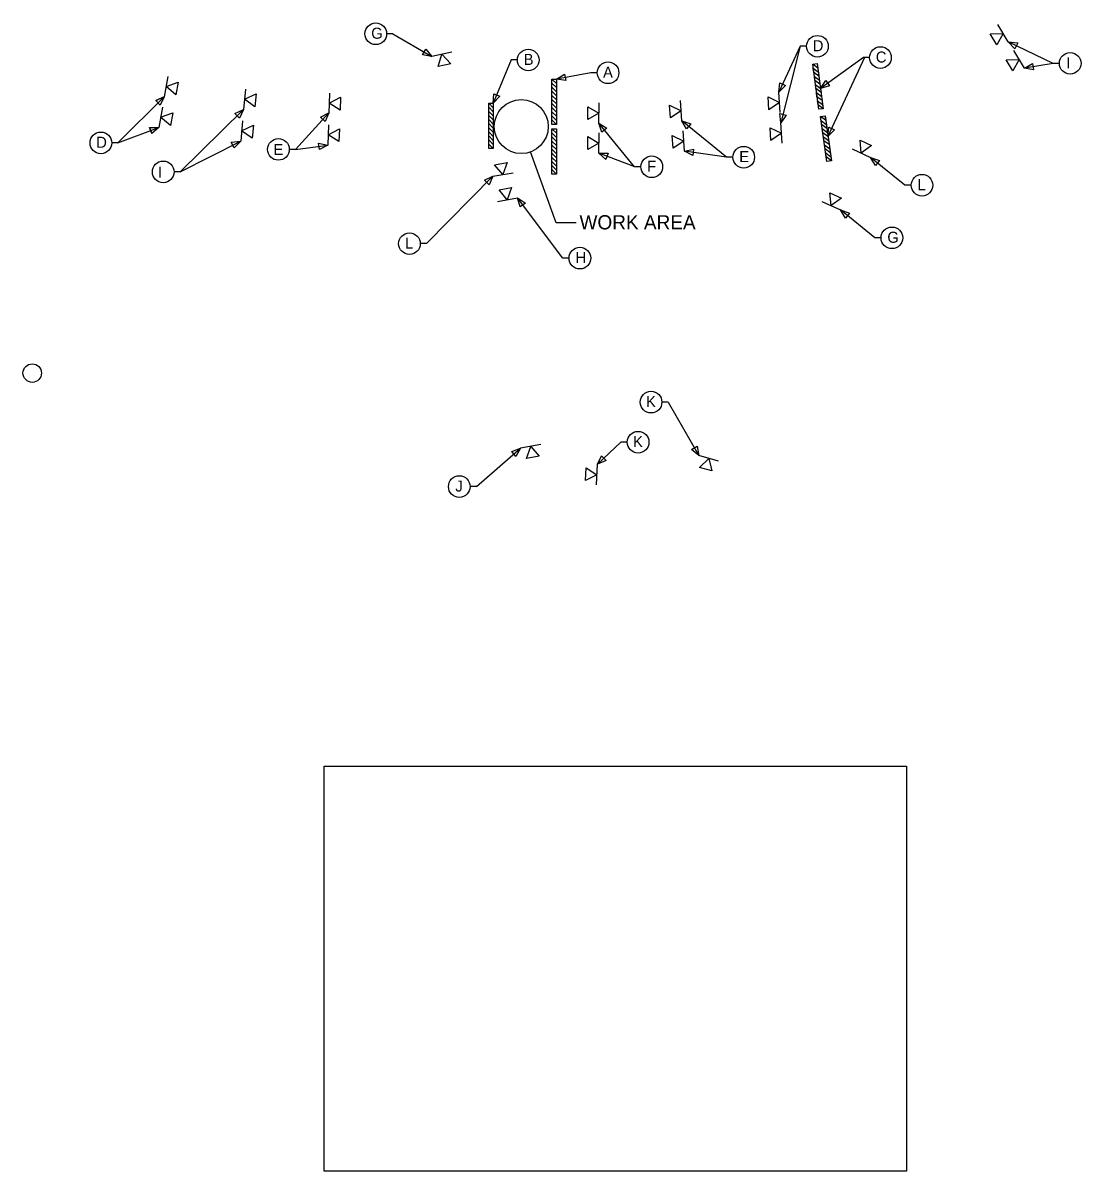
# Model space of a CAD drawing. Extents: x 2157572 to 5059327, y 715220 to 1674494.
# Drawn here: x 2244468 to 2251167, y 723646 to 730920 of the extents above; entities that cross this region are included whole.
import ezdxf

# ---------------------------------------------------------------- set-up
doc = ezdxf.new("R2010")
doc.units = 0
for name, color, linetype in [('Exist Map Preparation Border Sheet 1 CELL', 7, 'Continuous'), ('Exist Road Primary US Structure Standard Bridge Number Label', 7, 'Continuous'), ('Exist Road Secondary Structure Pipe Number Label', 7, 'Continuous'), ('Exist Road Secondary Type 41 SR Number Label', 7, 'Continuous'), ('Level 51', 7, 'Continuous'), ('Map Preparation County Base Legend Highway Garage or Maintenance Office', 7, 'Continuous')]:
    doc.layers.add(name, color=color, linetype=linetype)

msp = doc.modelspace()

# ---------------------------------------------------------------- linework, layer by layer
at = {"layer": 'Exist Map Preparation Border Sheet 1 CELL'}
msp.add_lwpolyline([(2250061.6, 723646.4), (2246376, 723646.4), (2246376, 726211.5), (2250061.6, 726211.5)], close=True, dxfattribs=at)
at = {"layer": 'Exist Road Secondary Structure Pipe Number Label'}
for p, q in [((2250707.1, 730799.8), (2250640, 730910.7)), ((2250592.7, 730852.2), (2250674.2, 730854.1)), ((2250634.8, 730782.8), (2250592.7, 730852.2)), ((2250674.2, 730854.1), (2250634.8, 730782.8)), ((2247183.1, 730736.2), (2247056.7, 730707.5)), ((2247097.3, 730644.2), (2247121.2, 730722.2)), ((2247121.2, 730722.2), (2247176.5, 730662.2)), ((2250694.3, 730686.9), (2250775.8, 730688.8)), ((2250736.4, 730617.4), (2250694.3, 730686.9)), ((2250775.8, 730688.8), (2250736.4, 730617.4)), ((2250808.7, 730634.5), (2250741.6, 730745.3)), ((2247176.5, 730662.2), (2247097.3, 730644.2)), ((2245385.6, 730580.5), (2245362.6, 730453)), ((2245374.3, 730518), (2245451.1, 730545.4)), ((2245451.1, 730545.4), (2245436.7, 730465.5)), ((2245436.7, 730465.5), (2245374.3, 730518)), ((2245876, 730500.2), (2245864, 730371.2)), ((2245870.1, 730437), (2245944.3, 730470.9)), ((2245944.3, 730470.9), (2245936.7, 730390)), ((2246409.1, 730475.6), (2246404, 730346.1)), ((2249263.2, 730352.4), (2249254.4, 730481.7)), ((2245351, 730386), (2245328, 730258.5)), ((2245936.7, 730390), (2245870.1, 730437)), ((2246406.6, 730412.1), (2246478.8, 730449.9)), ((2246475.7, 730368.8), (2246406.6, 730412.1)), ((2246478.8, 730449.9), (2246475.7, 730368.8)), ((2248043.8, 730308.5), (2248045.1, 730389.7)), ((2248045.1, 730389.7), (2248115.1, 730348)), ((2248114.1, 730284.5), (2248116.2, 730414.1)), ((2248562.3, 730399.5), (2248635.6, 730363.8)), ((2248567.9, 730318.5), (2248562.3, 730399.5)), ((2248639.9, 730300.5), (2248631.1, 730429.8)), ((2249185.6, 730451.5), (2249258.9, 730415.8)), ((2249191.1, 730370.5), (2249185.6, 730451.5)), ((2249258.9, 730415.8), (2249191.1, 730370.5)), ((2245339.8, 730323.5), (2245416.5, 730350.9)), ((2245402.1, 730271.1), (2245339.8, 730323.5)), ((2245416.5, 730350.9), (2245402.1, 730271.1)), ((2248115.1, 730348), (2248043.8, 730308.5)), ((2248635.6, 730363.8), (2248567.9, 730318.5)), ((2245858.6, 730301.2), (2245846.6, 730172.2)), ((2245852.7, 730238), (2245926.8, 730271.9)), ((2245926.8, 730271.9), (2245919.3, 730191.1)), ((2246402.4, 730275.9), (2246397.4, 730146.4)), ((2246399.9, 730212.5), (2246472.1, 730250.3)), ((2246472.1, 730250.3), (2246469, 730169.2)), ((2249198.3, 730257), (2249271.6, 730221.3)), ((2249203.8, 730176), (2249198.3, 730257)), ((2249275.9, 730157.9), (2249267.1, 730287.2)), ((2245919.3, 730191.1), (2245852.7, 730238)), ((2246469, 730169.2), (2246399.9, 730212.5)), ((2248043.8, 730119.5), (2248045.1, 730200.7)), ((2248045.1, 730200.7), (2248115.1, 730158.9)), ((2248114.1, 730095.4), (2248116.2, 730225)), ((2248578.7, 730207.7), (2248651.9, 730172)), ((2248584.2, 730126.7), (2248578.7, 730207.7)), ((2248651.9, 730172), (2248584.2, 730126.7)), ((2248656.3, 730108.6), (2248647.5, 730237.9)), ((2249271.6, 730221.3), (2249203.8, 730176)), ((2249775.3, 730096.5), (2249768, 730177.7)), ((2249768, 730177.7), (2249841.7, 730143.8)), ((2248115.1, 730158.9), (2248043.8, 730119.5)), ((2249717.6, 730123.1), (2249835.3, 730068.9)), ((2249841.7, 730143.8), (2249775.3, 730096.5)), ((2247454.5, 730022.3), (2247534.4, 730036.3)), ((2247506.6, 729959.7), (2247454.5, 730022.3)), ((2247534.4, 730036.3), (2247506.6, 729959.7)), ((2247444, 729948.8), (2247571.7, 729971)), ((2247482.2, 729863), (2247562.1, 729876.9)), ((2247562.1, 729876.9), (2247534.3, 729800.3)), ((2247471.7, 729789.4), (2247599.4, 729811.6)), ((2247534.3, 729800.3), (2247482.2, 729863)), ((2249584.8, 729763), (2249577.2, 729844.2)), ((2249577.2, 729844.2), (2249651, 729810.5)), ((2249651, 729810.5), (2249584.8, 729763)), ((2249527, 729789.3), (2249645, 729735.6)), ((2247746, 728248.8), (2247618.3, 728226.6)), ((2247655.6, 728161.3), (2247683.5, 728237.9)), ((2247683.5, 728237.9), (2247735.6, 728175.2)), ((2247735.6, 728175.2), (2247655.6, 728161.3)), ((2248871.8, 728144), (2248747.2, 728179.7)), ((2248752.2, 728104.7), (2248810.7, 728161.5)), ((2248810.7, 728161.5), (2248830.3, 728082.3)), ((2248029.7, 728020.9), (2248033.6, 728102)), ((2248102.3, 728058), (2248029.7, 728020.9)), ((2248033.6, 728102), (2248102.3, 728058)), ((2248099.2, 727994.6), (2248105.5, 728124.1)), ((2248830.3, 728082.3), (2248752.2, 728104.7))]:
    msp.add_line(p, q, dxfattribs=at)
at = {"layer": 'Exist Road Secondary Type 41 SR Number Label'}
for p, q in [((2249468.7, 730658.9), (2249497.3, 730662.6)), ((2249501, 730634.5), (2249468.7, 730658.9)), ((2249469.2, 730659), (2249497.3, 730662.6)), ((2249506.4, 730373.5), (2249469.2, 730659)), ((2249472.1, 730633.2), (2249504.3, 730608.8)), ((2249475.4, 730607.5), (2249472.1, 730633.2)), ((2249507.7, 730583.2), (2249475.4, 730607.5)), ((2249497.3, 730662.6), (2249501, 730634.5)), ((2249497.3, 730662.6), (2249534.5, 730377.2)), ((2249504.3, 730608.8), (2249507.7, 730583.2)), ((2247817, 730565.2), (2247845.8, 730565.2)), ((2247845.8, 730536.9), (2247817, 730565.2)), ((2247817, 730539.3), (2247845.8, 730511)), ((2247817, 730513.4), (2247817, 730539.3)), ((2247817.5, 730277.4), (2247817.5, 730565.2)), ((2247817.5, 730565.2), (2247845.8, 730565.2)), ((2247845.8, 730565.2), (2247845.8, 730536.9)), ((2247845.8, 730565.2), (2247845.8, 730277.4)), ((2249478.8, 730581.9), (2249511, 730557.5)), ((2249482.1, 730556.2), (2249478.8, 730581.9)), ((2249514.4, 730531.8), (2249482.1, 730556.2)), ((2249485.5, 730530.5), (2249517.7, 730506.1)), ((2249488.8, 730504.8), (2249485.5, 730530.5)), ((2249511, 730557.5), (2249514.4, 730531.8)), ((2247845.8, 730485.1), (2247817, 730513.4)), ((2247817, 730487.5), (2247845.8, 730459.2)), ((2247817, 730461.6), (2247817, 730487.5)), ((2247845.8, 730433.3), (2247817, 730461.6)), ((2247845.8, 730511), (2247845.8, 730485.1)), ((2247845.8, 730459.2), (2247845.8, 730433.3)), ((2249521.1, 730480.4), (2249488.8, 730504.8)), ((2249492.2, 730479.1), (2249524.5, 730454.3)), ((2249495.5, 730453.4), (2249492.2, 730479.1)), ((2249517.7, 730506.1), (2249521.1, 730480.4)), ((2247417.4, 730412), (2247446.2, 730412)), ((2247446.2, 730383.7), (2247417.4, 730412)), ((2247417.4, 730386.1), (2247446.2, 730357.8)), ((2247417.4, 730360.2), (2247417.4, 730386.1)), ((2247417.9, 730124.2), (2247417.9, 730412)), ((2247417.9, 730412), (2247446.2, 730412)), ((2247446.2, 730412), (2247446.2, 730383.7)), ((2247446.2, 730412), (2247446.2, 730124.2)), ((2247817, 730435.7), (2247845.8, 730407.4)), ((2247817, 730409.8), (2247817, 730435.7)), ((2247845.8, 730381.5), (2247817, 730409.8)), ((2247845.8, 730407.4), (2247845.8, 730381.5)), ((2249527.8, 730428.6), (2249495.5, 730453.4)), ((2249498.9, 730427.8), (2249531.2, 730402.9)), ((2249502.2, 730402.1), (2249498.9, 730427.8)), ((2249534.5, 730377.2), (2249502.2, 730402.1)), ((2249524.5, 730454.3), (2249527.8, 730428.6)), ((2249531.2, 730402.9), (2249534.5, 730377.2)), ((2247446.2, 730331.9), (2247417.4, 730360.2)), ((2247417.4, 730334.3), (2247446.2, 730306)), ((2247417.4, 730308.4), (2247417.4, 730334.3)), ((2247446.2, 730357.8), (2247446.2, 730331.9)), ((2247817, 730383.9), (2247845.8, 730355.1)), ((2247817, 730358), (2247817, 730383.9)), ((2247845.8, 730329.2), (2247817, 730358)), ((2247817, 730332.1), (2247845.8, 730303.3)), ((2247817, 730306.2), (2247817, 730332.1)), ((2247845.8, 730355.1), (2247845.8, 730329.2)), ((2249534.5, 730377.2), (2249506.4, 730373.5)), ((2249517.8, 730327.6), (2249546.4, 730331.7)), ((2249550.4, 730303.6), (2249517.8, 730327.6)), ((2249518.3, 730327.7), (2249546.4, 730331.7)), ((2249558.9, 730042.7), (2249518.3, 730327.7)), ((2249546.4, 730331.7), (2249550.4, 730303.6)), ((2249546.4, 730331.7), (2249587, 730046.7)), ((2247446.2, 730280.1), (2247417.4, 730308.4)), ((2247417.4, 730282.5), (2247446.2, 730254.2)), ((2247417.4, 730256.6), (2247417.4, 730282.5)), ((2247446.2, 730228.3), (2247417.4, 730256.6)), ((2247446.2, 730306), (2247446.2, 730280.1)), ((2247446.2, 730254.2), (2247446.2, 730228.3)), ((2247845.8, 730277.4), (2247817, 730306.2)), ((2247817, 730250), (2247845.8, 730250)), ((2247845.8, 730221.6), (2247817, 730250)), ((2247845.8, 730277.4), (2247817.5, 730277.4)), ((2247817.5, 729962.1), (2247817.5, 730250)), ((2247817.5, 730250), (2247845.8, 730250)), ((2247845.8, 730303.3), (2247845.8, 730277.4)), ((2247845.8, 730250), (2247845.8, 730221.6)), ((2247845.8, 730250), (2247845.8, 729962.1)), ((2249521.5, 730302), (2249554, 730278)), ((2249525.1, 730276.4), (2249521.5, 730302)), ((2249557.7, 730252.4), (2249525.1, 730276.4)), ((2249528.8, 730250.7), (2249561.3, 730226.7)), ((2249532.4, 730225.1), (2249528.8, 730250.7)), ((2249554, 730278), (2249557.7, 730252.4)), ((2247417.4, 730230.7), (2247446.2, 730201.9)), ((2247417.4, 730204.8), (2247417.4, 730230.7)), ((2247446.2, 730176), (2247417.4, 730204.8)), ((2247417.4, 730178.9), (2247446.2, 730150.1)), ((2247417.4, 730153), (2247417.4, 730178.9)), ((2247446.2, 730201.9), (2247446.2, 730176)), ((2247817, 730224.1), (2247845.8, 730195.7)), ((2247817, 730198.2), (2247817, 730224.1)), ((2247845.8, 730169.8), (2247817, 730198.2)), ((2247817, 730172.3), (2247845.8, 730143.9)), ((2247817, 730146.4), (2247817, 730172.3)), ((2247845.8, 730195.7), (2247845.8, 730169.8)), ((2249565, 730201.1), (2249532.4, 730225.1)), ((2249536.1, 730199.4), (2249568.7, 730175.4)), ((2249539.8, 730173.8), (2249536.1, 730199.4)), ((2249572.3, 730149.8), (2249539.8, 730173.8)), ((2249561.3, 730226.7), (2249565, 730201.1)), ((2249568.7, 730175.4), (2249572.3, 730149.8)), ((2247446.2, 730124.2), (2247417.4, 730153)), ((2247446.2, 730124.2), (2247417.9, 730124.2)), ((2247446.2, 730150.1), (2247446.2, 730124.2)), ((2247845.8, 730118), (2247817, 730146.4)), ((2247817, 730120.5), (2247845.8, 730092.1)), ((2247817, 730094.6), (2247817, 730120.5)), ((2247845.8, 730066.2), (2247817, 730094.6)), ((2247845.8, 730143.9), (2247845.8, 730118)), ((2249543.4, 730148.1), (2249576, 730123.7)), ((2249547.1, 730122.5), (2249543.4, 730148.1)), ((2249579.7, 730098), (2249547.1, 730122.5)), ((2249550.7, 730096.9), (2249583.3, 730072.4)), ((2249554.4, 730071.2), (2249550.7, 730096.9)), ((2249576, 730123.7), (2249579.7, 730098)), ((2247817, 730068.7), (2247845.8, 730039.8)), ((2247817, 730042.8), (2247817, 730068.7)), ((2247845.8, 730013.9), (2247817, 730042.8)), ((2247845.8, 730092.1), (2247845.8, 730066.2)), ((2247845.8, 730039.8), (2247845.8, 730013.9)), ((2249587, 730046.7), (2249554.4, 730071.2)), ((2249587, 730046.7), (2249558.9, 730042.7)), ((2249583.3, 730072.4), (2249587, 730046.7)), ((2247817, 730016.9), (2247845.8, 729988)), ((2247817, 729991), (2247817, 730016.9)), ((2247845.8, 729962.1), (2247817, 729991)), ((2247845.8, 729962.1), (2247817.5, 729962.1)), ((2247845.8, 729988), (2247845.8, 729962.1))]:
    msp.add_line(p, q, dxfattribs=at)
at = {"layer": 'Level 51'}
for p, q in [((2246810.1, 730851.8), (2246770.5, 730851.8)), ((2246810.1, 730851.8), (2247056.7, 730707.5)), ((2249390, 730772.6), (2249254.4, 730481.7)), ((2249390, 730772.6), (2249267.1, 730287.2)), ((2249429.6, 730772.6), (2249390, 730772.6)), ((2250990.6, 730664.6), (2250707.1, 730799.8)), ((2247559.3, 730685.8), (2247446.2, 730412)), ((2247598.9, 730685.8), (2247559.3, 730685.8)), ((2249789.4, 730700.9), (2249517.7, 730506.1)), ((2249797.1, 730700.9), (2249565, 730201.1)), ((2249829, 730700.9), (2249789.4, 730700.9)), ((2248064.4, 730604.9), (2247845.8, 730565.2)), ((2248104, 730604.9), (2248064.4, 730604.9)), ((2250990.6, 730664.6), (2250808.7, 730634.5)), ((2251030.2, 730664.6), (2250990.6, 730664.6)), ((2245069.5, 730160.8), (2245362.6, 730453)), ((2245362.6, 730453), (2245308.2, 730428.1)), ((2245308.2, 730428.1), (2245337.5, 730398.7)), ((2245362.6, 730453), (2245337.5, 730398.7)), ((2245464.1, 729976.5), (2245864, 730371.2)), ((2246193.9, 730119.5), (2246404.2, 730351)), ((2245069.5, 730160.8), (2245328, 730258.5)), ((2245268.3, 730258.1), (2245282.9, 730219.3)), ((2248340.9, 730009), (2248114.1, 730284.5)), ((2248923.2, 730070), (2248639.9, 730300.5)), ((2245464.1, 729976.5), (2245846.6, 730172.2)), ((2245069.5, 730160.8), (2245029.9, 730160.8)), ((2246193.9, 730119.5), (2246154.3, 730119.5)), ((2246193.9, 730119.5), (2246397.4, 730146.4)), ((2247844.2, 729654.2), (2247681.7, 730103.4)), ((2248342.5, 730008.4), (2248114.1, 730095.4)), ((2248923.2, 730070), (2248656.3, 730108.6)), ((2248962.8, 730070), (2248923.2, 730070)), ((2250052.3, 729892.2), (2249835.3, 730068.9)), ((2245464.1, 729976.5), (2245424.5, 729976.5)), ((2247023.7, 729522.1), (2247444, 729948.8)), ((2248380.5, 730009), (2248340.9, 730009)), ((2250091.9, 729892.2), (2250052.3, 729892.2)), ((2247885.9, 729430.4), (2247599.4, 729811.6)), ((2249861.9, 729559), (2249645, 729735.6)), ((2247969.9, 729654.2), (2247844.2, 729654.2)), ((2247023.7, 729522.1), (2246984.1, 729522.1)), ((2249901.5, 729559), (2249861.9, 729559)), ((2247925.5, 729430.4), (2247885.9, 729430.4)), ((2248553, 728517.9), (2248513.4, 728517.9)), ((2248553, 728517.9), (2248747.2, 728179.7)), ((2247339.1, 727982.9), (2247618.3, 728226.6)), ((2248254.4, 728264.3), (2248105.5, 728124.1)), ((2248294, 728264.3), (2248254.4, 728264.3)), ((2247339.1, 727982.9), (2247299.5, 727982.9))]:
    msp.add_line(p, q, dxfattribs=at)
for points in [[(2246997.9, 730717.9), (2247018.8, 730753.7), (2247056.7, 730707.5)], [(2250766.6, 730794.4), (2250748.8, 730757), (2250707.1, 730799.8)], [(2250860.6, 730664.1), (2250867.4, 730623.2), (2250808.7, 730634.5)], [(2247897.3, 730595.6), (2247904.7, 730554.8), (2247845.8, 730565.2)], [(2249259.3, 730541.3), (2249296.9, 730523.8), (2249254.4, 730481.7)], [(2249551.2, 730555.6), (2249575.4, 730521.9), (2249517.7, 730506.1)], [(2247448.5, 730471.8), (2247486.8, 730455.9), (2247446.2, 730412)], [(2245337.5, 730398.7), (2245308.2, 730428.1), (2245362.6, 730453)], [(2245838.7, 730317.1), (2245809.5, 730346.6), (2245864, 730371.2)], [(2246381.9, 730295.6), (2246351.2, 730323.5), (2246404.2, 730351)], [(2249260.8, 730346.6), (2249301, 730336.5), (2249267.1, 730287.2)], [(2245282.9, 730219.3), (2245268.3, 730258.1), (2245328, 730258.5)], [(2248165.7, 730254.4), (2248133.7, 730228), (2248114.1, 730284.5)], [(2248696.5, 730281.2), (2248670.3, 730249), (2248639.9, 730300.5)], [(2249569.8, 730260.7), (2249607.4, 730243.2), (2249565, 730201.1)], [(2245806.1, 730128.2), (2245787.2, 730165.1), (2245846.6, 730172.2)], [(2246344.5, 730118.5), (2246339.1, 730159.6), (2246397.4, 730146.4)], [(2248173.8, 730094.9), (2248159.1, 730056.1), (2248114.1, 730095.4)], [(2248714.7, 730121.1), (2248708.8, 730080.1), (2248656.3, 730108.6)], [(2249891.9, 730049.6), (2249865.7, 730017.4), (2249835.3, 730068.9)], [(2247419.4, 729894.3), (2247389.9, 729923.4), (2247444, 729948.8)], [(2247649.6, 729779.3), (2247616.5, 729754.4), (2247599.4, 729811.6)], [(2249701.5, 729716.3), (2249675.3, 729684.2), (2249645, 729735.6)], [(2247589.7, 728174.1), (2247562.5, 728205.3), (2247618.3, 728226.6)], [(2248701.3, 728218), (2248737.3, 728238.6), (2248747.2, 728179.7)], [(2248132.1, 728177.6), (2248160.5, 728147.4), (2248105.5, 728124.1)]]:
    msp.add_lwpolyline(points, close=True, dxfattribs=at)
for centre, radius in [((2246701.9, 730851.8), 68.6), ((2249498.2, 730772.6), 68.6), ((2247667.5, 730685.8), 68.6), ((2249897.6, 730700.9), 68.6), ((2251098.8, 730664.6), 68.6), ((2248172.6, 730604.9), 68.6), ((2247623.1, 730264), 171), ((2244961.2, 730160.8), 68.6), ((2246085.6, 730119.5), 68.6), ((2249031.5, 730070), 68.6), ((2245355.8, 729976.5), 68.6), ((2248449.2, 730009), 68.6), ((2250160.5, 729892.2), 68.6), ((2246915.4, 729522.1), 68.6), ((2249970.2, 729559), 68.6), ((2247994.1, 729430.4), 68.6), ((2244526.7, 728702.1), 58.7), ((2248444.8, 728517.9), 68.6), ((2248362.7, 728264.3), 68.6), ((2247230.8, 727982.9), 68.6)]:
    msp.add_circle(centre, radius, dxfattribs=at)
at = {"layer": 'Map Preparation County Base Legend Highway Garage or Maintenance Office'}
for centre in [(2246701.9, 730851.8), (2249498.2, 730772.6), (2247667.5, 730685.8), (2249897.6, 730700.9), (2251098.8, 730664.6), (2248172.6, 730604.9), (2244961.2, 730160.8), (2246085.6, 730119.5), (2249031.5, 730070), (2245355.8, 729976.5), (2248449.2, 730009), (2250160.5, 729892.2), (2246915.4, 729522.1), (2249970.2, 729559), (2247994.1, 729430.4), (2248444.8, 728517.9), (2248362.7, 728264.3), (2247230.8, 727982.9)]:
    msp.add_circle(centre, 68.6, dxfattribs=at)

# ---------------------------------------------------------------- texts
at = {"layer": 'Exist Road Primary US Structure Standard Bridge Number Label'}
msp.add_text('WORK AREA', height=90, dxfattribs=at).set_placement((2247991.8, 729612.6))
at = {"layer": 'Level 51'}
for s, p in [('G', (2246672.8, 730820.4)), ('D', (2249468.8, 730741.2)), ('B', (2247638.5, 730654.3)), ('C', (2249868.1, 730669.5)), ('I', (2251073.8, 730633.2)), ('A', (2248141, 730573.5)), ('D', (2244931.8, 730129.4)), ('E', (2246053.4, 730083.6)), ('E', (2249003.4, 730038.6)), ('F', (2248420.2, 729977.6)), ('I', (2245323.5, 729939.5)), ('L', (2250131.8, 729860.8)), ('G', (2249941.1, 729527.6)), ('L', (2246886.8, 729490.7)), ('H', (2247966, 729399)), ('K', (2248413, 728486.5)), ('K', (2248330.9, 728232.9)), ('J', (2247205.9, 727951.4))]:
    msp.add_text(s, height=70, dxfattribs=at).set_placement(p)

doc.saveas('drawing.dxf')
